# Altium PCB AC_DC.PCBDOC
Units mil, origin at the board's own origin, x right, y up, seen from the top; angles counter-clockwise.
Board outline 6000 x 4000 mil, 2 copper layers (Top Layer, Bottom Layer); 9 components, 7 nets, 23 pads, 0 vias.
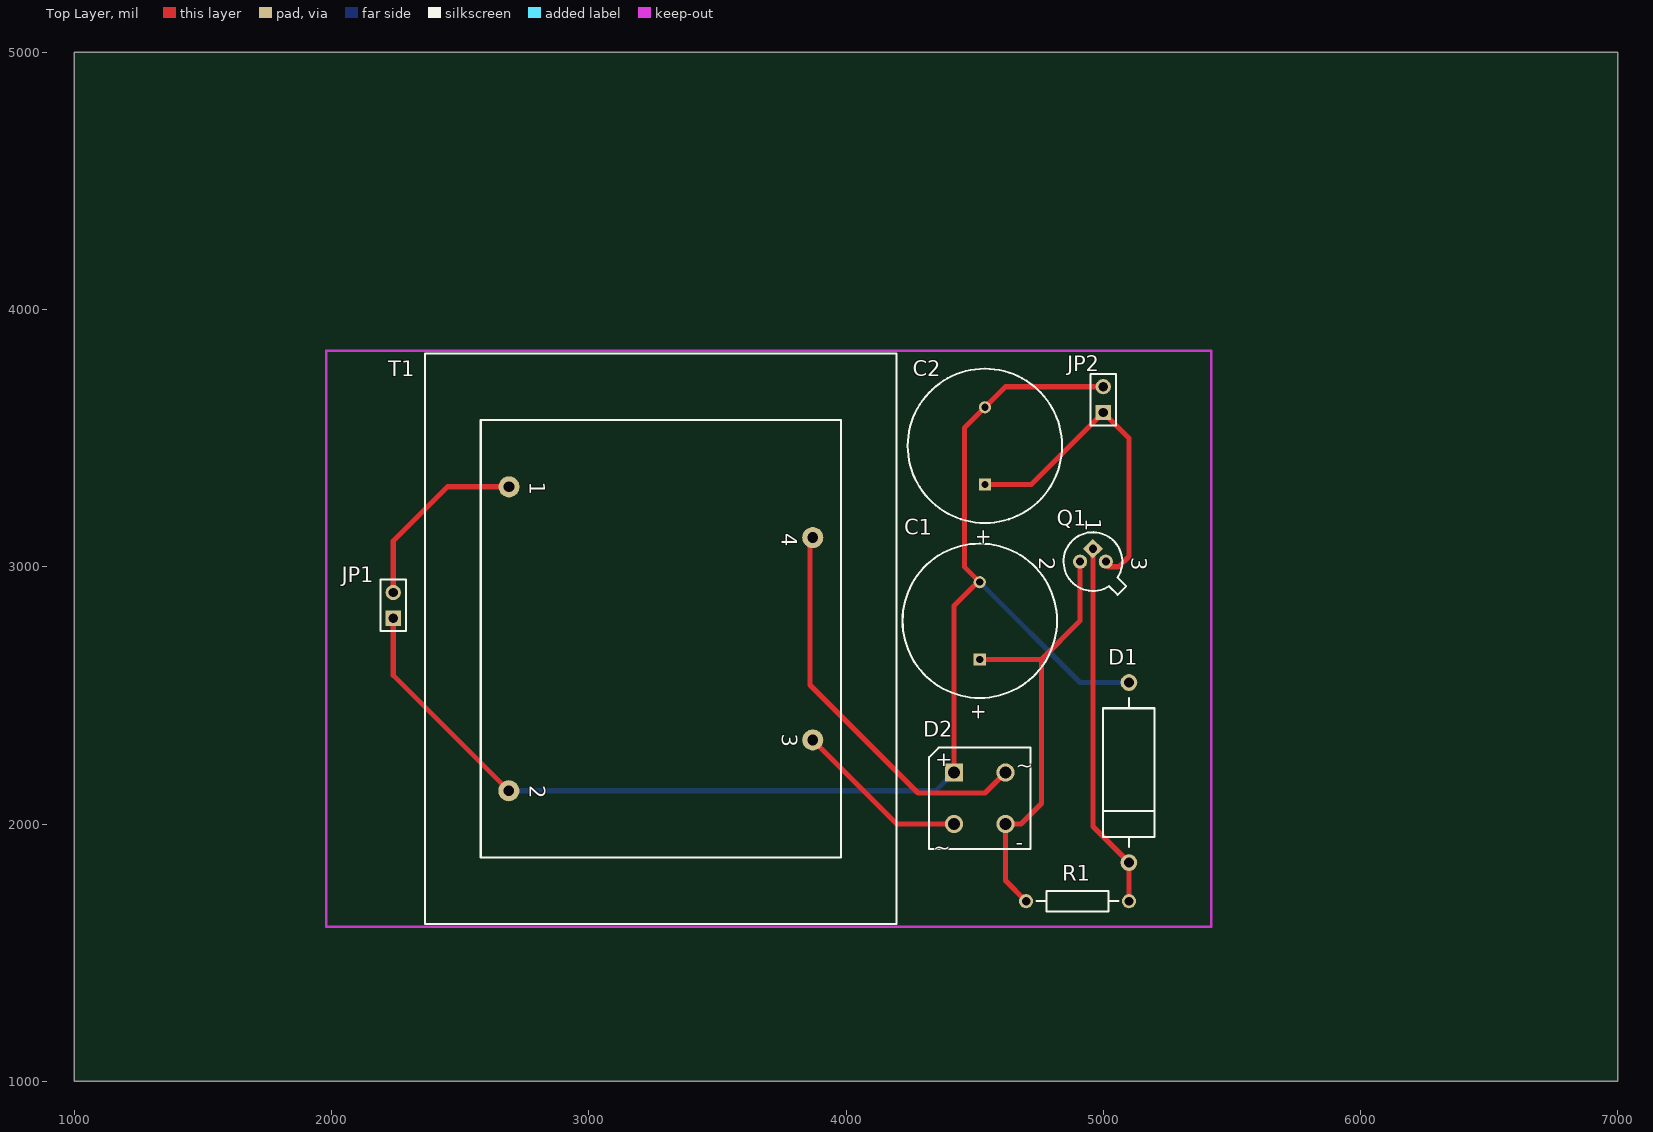
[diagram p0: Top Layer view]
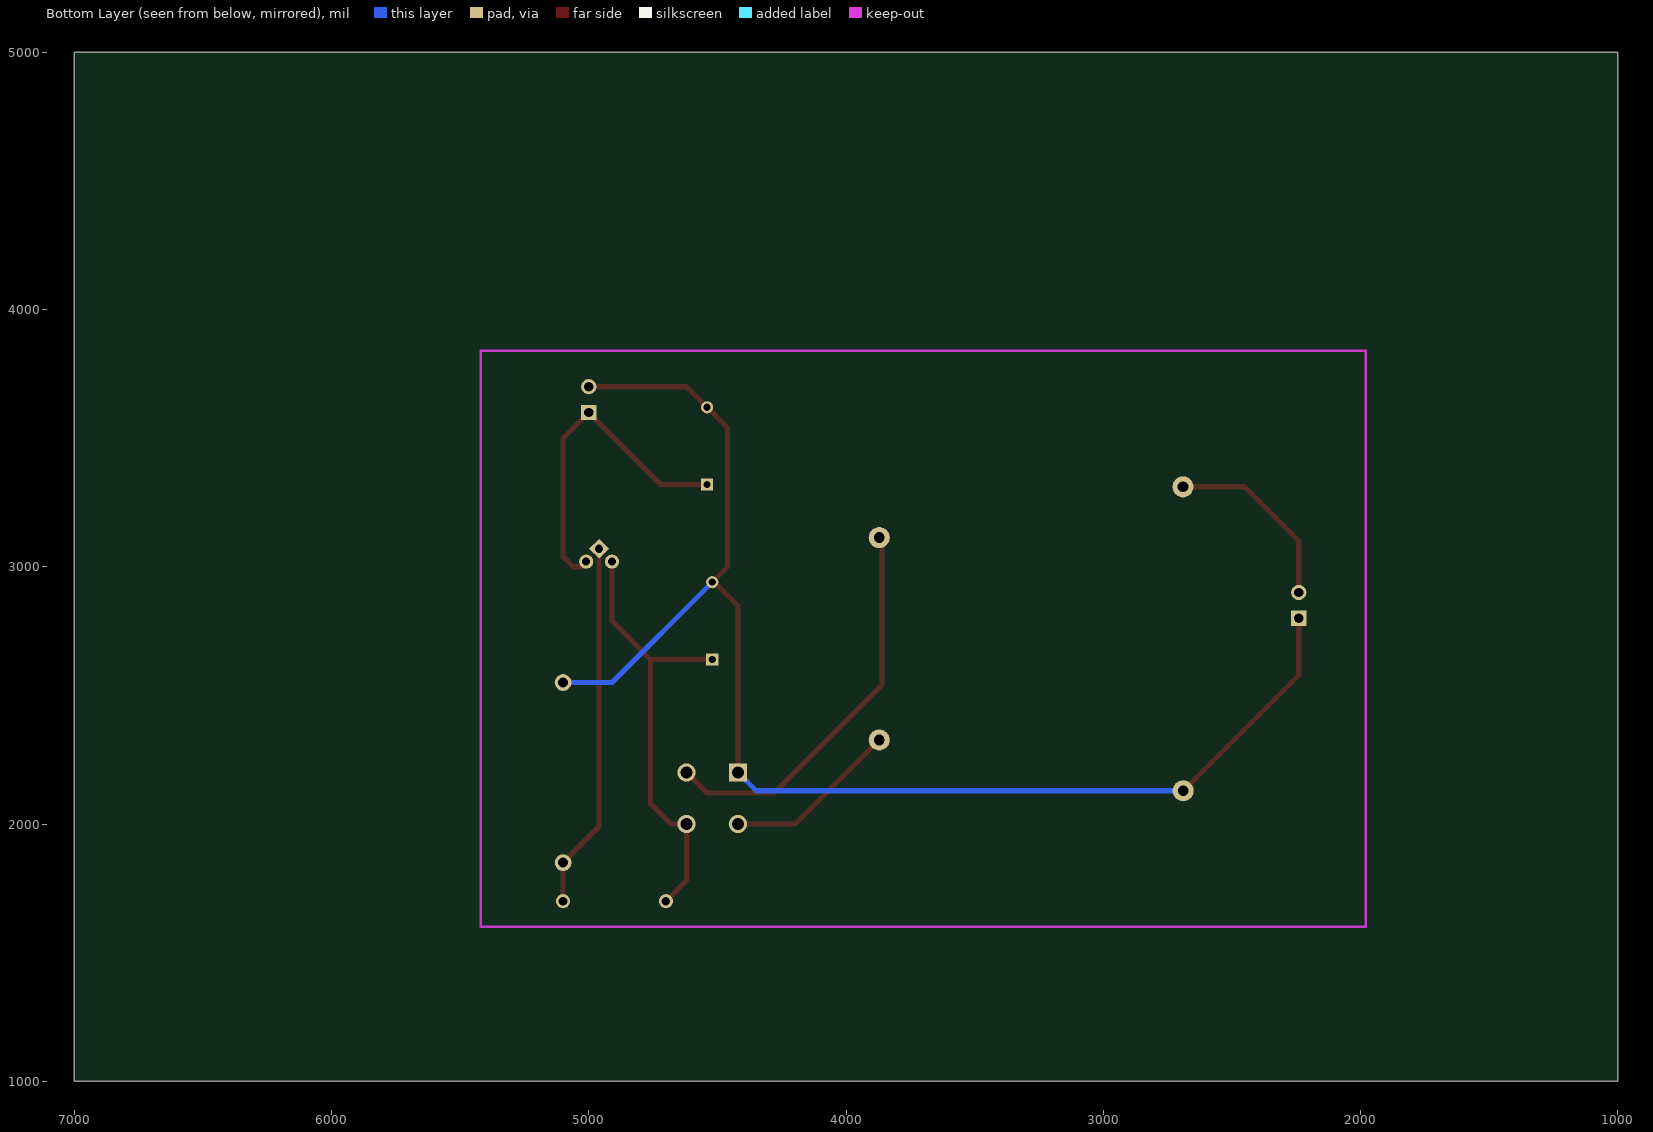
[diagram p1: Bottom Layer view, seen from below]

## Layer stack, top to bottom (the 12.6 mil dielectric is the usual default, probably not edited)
Top Layer: signal copper 1.4
Dielectric: dielectric 12.6, FR-4, Dk 4.8
Bottom Layer: signal copper 1.4

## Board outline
1000,1000 7000,1000 7000,5000 1000,5000

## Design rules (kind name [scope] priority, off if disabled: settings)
Clearance [All] p1: gap=10
ComponentClearance [All] p1: gap=10 collisioncheckmode=0
PolygonConnect [All] p1: connectstyle=Relief reliefconductorwidth=10 reliefentries=4 polygonreliefangle="90 Angle"
RoutingLayers [All] p1: top layer=Horizontal bottom layer=Vertical
RoutingVias [All] p1: holewidth=28 width=50 viastyle="Through Hole" minholewidth=28 minwidth=50 maxholewidth=28 maxwidth=50
SolderMaskExpansion [All] p1: expansion=4
TestPointUsage [All] p1: valid=0 allowmultiple=FALSE
Testpoint [All] p1: side=15 testpointundercomponent=TRUE minsize=40 maxsize=100 preferedsize=60 minholesize=0 maxholesize=40 preferedholesize=32 testpointgrid=1 style=1023 order=-539222988
Width [All] p1: maxlimit=50 minlimit=10 preferedwidth=20
16 further rules are at their usual default settings.

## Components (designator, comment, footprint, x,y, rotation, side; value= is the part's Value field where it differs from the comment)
C1 "Cap Pol1" RB7.6-15 4520,2640 r270 top
C2 "Cap Pol1" RB7.6-15 4540,3320 r270 top
D1 "D Zener" DIODE-0.7 5100,2200 r270 top
D2 "Bridge1" E-BIP-P4/D10 4520,2100 r0 top
JP1 "Header 2" HDR1X2 2240,2800 r90 top
JP2 "Header 2" HDR1X2 5000,3600 r90 top
Q1 "2N2222A" CAN-3/D5.8 4960,3020 r270 top
R1 "680" AXIAL-0.4 4900,1700 r180 top
T1 "Trans Ideal" TRF_4 3280,2720 r270 top

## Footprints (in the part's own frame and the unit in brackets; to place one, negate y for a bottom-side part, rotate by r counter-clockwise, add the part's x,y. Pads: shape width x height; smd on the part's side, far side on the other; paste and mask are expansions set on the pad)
AXIAL-0.4 [mm]
  round 1.4 hole 0.85: 1(-5.08,0) 2(5.08,0)
  silkscreen extent -4.06,-1.02 4.06,1.02
CAN-3/D5.8 [mm]
  rect 1.4x1.4 hole 0.8 rot 45: 1(-1.27,0)
  round 1.4 hole 0.8: 2(0,-1.27) 3(0,1.27)
  silkscreen extent -2.9,-2.9 3.28,3.28
DIODE-0.7 [mm]
  round 1.65 hole 1: 1(-8.89,0) 2(8.89,0)
  silkscreen extent -7.37,-2.54 7.37,2.54
E-BIP-P4/D10 [mm]
  rect 1.8x1.8 hole 1.2: 1(-2.54,2.54)
  round 1.8 hole 1.2: 2(-2.54,-2.54) 3(2.54,-2.54) 4(2.54,2.54)
  silkscreen extent -5,-5 5,5
HDR1X2 [mm]
  rect 1.5x1.5 hole 0.9: 1(0,0)
  round 1.5 hole 0.9: 2(2.54,0)
  silkscreen extent -1.27,-1.27 3.81,1.27
RB7.6-15 [mm]
  rect 1.2x1.2 hole 0.7: 1(0,0)
  round 1.2 hole 0.7: 2(-7.62,0)
  silkscreen extent -11.43,-7.62 3.81,7.62
TRF_4 [mil]
  round 82 hole 42: 1(-590.83,-590) 2(590.83,-590.83) 3(393.33,590.83) 4(-393.33,590.83)
  silkscreen extent -1108,-917 1108,917

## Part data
C1 C2: "Polarized Capacitor (Radial)"
D1: "Zener Diode"
D2: "Full Wave Diode Bridge"
JP1 JP2: "Header, 2-Pin"
Q1: "High Speed Switches"
R1: library part Res2, "Resistor"
T1: "Transformer (Ideal)"

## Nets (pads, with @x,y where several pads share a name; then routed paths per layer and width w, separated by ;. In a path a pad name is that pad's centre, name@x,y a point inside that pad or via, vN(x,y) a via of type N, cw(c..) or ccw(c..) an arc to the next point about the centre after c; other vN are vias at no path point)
GND: C1.2 C2.2 D1.1 D2.1 JP1.1 JP2.2 T1.2 | length 5373.7
  Top Layer w20: JP1.1 2240,2578.34 T1.2 ; D2.1 4420,2848.59 C1.2@4515.71,2944.29 ; C1.2 4460,3000 4460,3540 4620,3700 JP2.2
  Bottom Layer w20: T1.2 4349.17,2129.17 D2.1 ; C1.2 4910,2550 D1.1
NetC1_1: C1.1 D2.3 Q1.2 R1.2 | length 1748.4
  Top Layer w20: C1.1 4760,2640 ; R1.2 4620,1780 D2.3 4680,2000 4760,2080 4760,2640 ; Q1.2 4910,2790 4760,2640
NetC2_1: C2.1 JP2.1 Q1.3 | length 1274
  Top Layer w20: C2.1 4720,3320 JP2.1 5100,3500 5100,3040 5060,3000 Q1.3@5020,3000
NetD1_2: D1.2 Q1.1 R1.1 | length 1428
  Top Layer w20: Q1.1 4960,1990 D1.2 R1.1
NetD2_2: D2.2 T1.3 | length 684.5
  Top Layer w20: T1.3 4197.5,2000 D2.2
NetD2_4: D2.4 T1.4 | length 1547.1
  Top Layer w20: T1.4@3860,3120 3860,2540 4280,2120 4540,2120 D2.4
NetJP1_2: JP1.2 T1.1 | length 737.3
  Top Layer w20: JP1.2 2240,3100 2450.83,3310.83 T1.1

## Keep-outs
Keep-Out Layer:
  lines w10: 1980,1600 1980,3640 1980,3840 5420,3840 5420,1600 1980,1600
